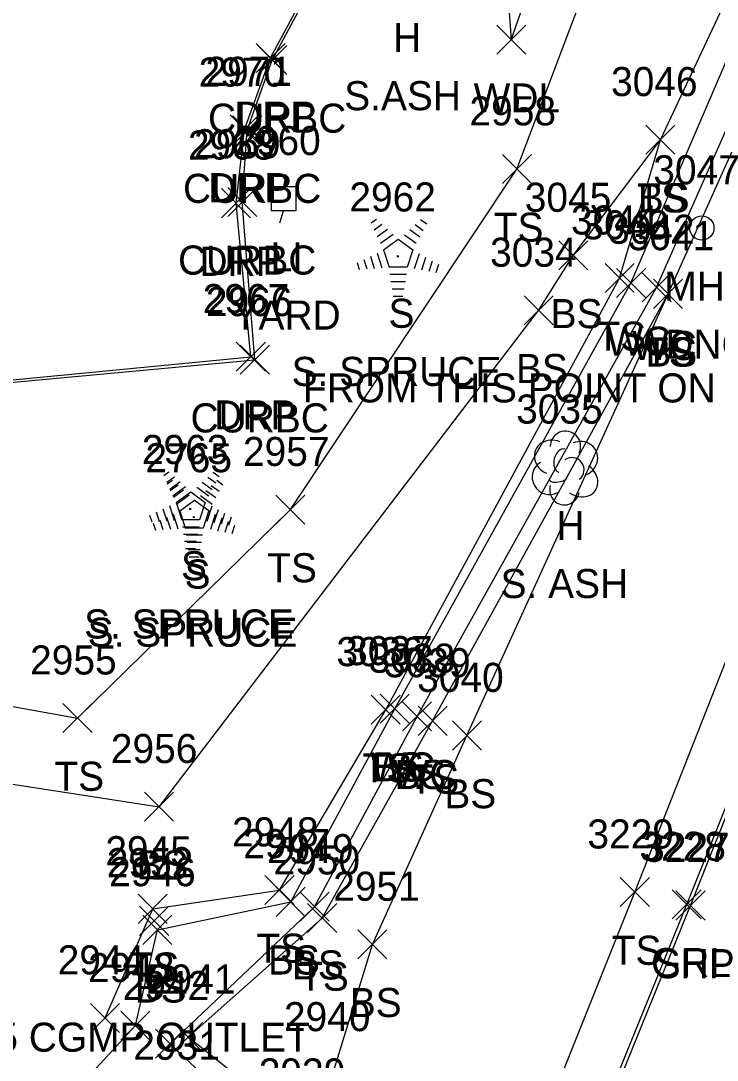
# Model space of a CAD drawing. Extents: x 1623612 to 1625808, y 621345 to 627748.
# Drawn here: x 1624785.9 to 1624833.8, y 626674 to 626745.5 of the extents above; entities that cross this region are included whole.
import ezdxf

# ---------------------------------------------------------------- set-up
doc = ezdxf.new("R2010")
doc.units = 0
for name, color, linetype in [('D_A', 7, 'Continuous'), ('D_C', 7, 'Continuous'), ('D_I', 7, 'Continuous'), ('D_TIC', 7, 'Continuous'), ('L_A', 7, 'Continuous'), ('L_C', 7, 'Continuous'), ('L_I', 7, 'Continuous'), ('L_TIC', 7, 'Continuous'), ('LAWA', 7, 'Continuous'), ('LAWE', 7, 'Continuous'), ('LELB', 7, 'Continuous'), ('LTC', 7, 'Continuous'), ('LTD', 7, 'Continuous'), ('P_A', 7, 'Continuous'), ('P_I', 7, 'Continuous'), ('P_TIC', 7, 'Continuous'), ('PSP', 7, 'Continuous'), ('R_A', 7, 'Continuous'), ('R_I', 7, 'Continuous'), ('R_TIC', 7, 'Continuous'), ('RC', 7, 'Continuous'), ('RDP', 7, 'Continuous'), ('RGR', 7, 'Continuous'), ('U_A', 7, 'Continuous'), ('U_C', 7, 'Continuous'), ('U_I', 7, 'Continuous'), ('ULP', 7, 'Continuous'), ('USMH', 7, 'Continuous')]:
    doc.layers.add(name, color=color, linetype=linetype)

msp = doc.modelspace()

# ---------------------------------------------------------------- linework, layer by layer
at = {"layer": 'D_TIC'}
for points in [[(1624794.045, 626682.576), (1624796.045, 626684.576)], [(1624796.045, 626682.576), (1624794.045, 626684.576)]]:
    msp.add_lwpolyline(points, dxfattribs=at)
at = {"layer": 'L_TIC'}
for points in [[(1624818.593, 626743.177), (1624820.593, 626745.177)], [(1624820.593, 626743.177), (1624818.593, 626745.177)], [(1624828.851, 626736.3), (1624830.851, 626738.3)], [(1624830.851, 626736.3), (1624828.851, 626738.3)], [(1624828.851, 626736.3), (1624830.851, 626738.3)], [(1624830.851, 626736.3), (1624828.851, 626738.3)], [(1624818.983, 626734.285), (1624820.983, 626736.285)], [(1624820.983, 626734.285), (1624818.983, 626736.285)], [(1624822.862, 626728.341), (1624824.862, 626730.341)], [(1624824.862, 626728.341), (1624822.862, 626730.341)], [(1624826.042, 626726.781), (1624828.042, 626728.781)], [(1624828.042, 626726.781), (1624826.042, 626728.781)], [(1624826.827, 626726.445), (1624828.827, 626728.445)], [(1624828.827, 626726.445), (1624826.827, 626728.445)], [(1624828.587, 626726.142), (1624830.587, 626728.142)], [(1624830.587, 626726.142), (1624828.587, 626728.142)], [(1624829.376, 626725.7), (1624831.376, 626727.7)], [(1624831.376, 626725.7), (1624829.376, 626727.7)], [(1624829.376, 626725.7), (1624831.376, 626727.7)], [(1624831.376, 626725.7), (1624829.376, 626727.7)], [(1624820.48, 626724.564), (1624822.48, 626726.564)], [(1624822.48, 626724.564), (1624820.48, 626726.564)], [(1624803.409, 626710.861), (1624805.409, 626712.861)], [(1624805.409, 626710.861), (1624803.409, 626712.861)], [(1624809.966, 626697.092), (1624811.966, 626699.092)], [(1624811.966, 626697.092), (1624809.966, 626699.092)], [(1624810.582, 626697.161), (1624812.582, 626699.161)], [(1624812.582, 626697.161), (1624810.582, 626699.161)], [(1624810.582, 626697.161), (1624812.582, 626699.161)], [(1624812.582, 626697.161), (1624810.582, 626699.161)], [(1624812.124, 626696.64), (1624814.124, 626698.64)], [(1624814.124, 626696.64), (1624812.124, 626698.64)], [(1624812.124, 626696.64), (1624814.124, 626698.64)], [(1624814.124, 626696.64), (1624812.124, 626698.64)], [(1624788.776, 626696.52), (1624790.776, 626698.52)], [(1624790.776, 626696.52), (1624788.776, 626698.52)], [(1624813.192, 626696.331), (1624815.192, 626698.331)], [(1624815.192, 626696.331), (1624813.192, 626698.331)], [(1624815.553, 626695.322), (1624817.553, 626697.322)], [(1624817.553, 626695.322), (1624815.553, 626697.322)], [(1624794.382, 626690.429), (1624796.382, 626692.429)], [(1624796.382, 626690.429), (1624794.382, 626692.429)], [(1624802.66, 626684.697), (1624804.66, 626686.697)], [(1624804.66, 626684.697), (1624802.66, 626686.697)], [(1624827.095, 626684.553), (1624829.095, 626686.553)], [(1624829.095, 626684.553), (1624827.095, 626686.553)], [(1624803.431, 626683.885), (1624805.431, 626685.885)], [(1624805.431, 626683.885), (1624803.431, 626685.885)], [(1624793.948, 626683.4), (1624795.948, 626685.4)], [(1624795.948, 626683.4), (1624793.948, 626685.4)], [(1624805.075, 626683.544), (1624807.075, 626685.544)], [(1624807.075, 626683.544), (1624805.075, 626685.544)], [(1624805.597, 626682.767), (1624807.597, 626684.767)], [(1624807.597, 626682.767), (1624805.597, 626684.767)], [(1624794.267, 626681.956), (1624796.267, 626683.956)], [(1624796.267, 626681.956), (1624794.267, 626683.956)], [(1624809.051, 626680.957), (1624811.051, 626682.957)], [(1624811.051, 626680.957), (1624809.051, 626682.957)], [(1624790.672, 626675.897), (1624792.672, 626677.897)], [(1624792.672, 626675.897), (1624790.672, 626677.897)], [(1624792.759, 626675.368), (1624794.759, 626677.368)], [(1624794.759, 626675.368), (1624792.759, 626677.368)], [(1624796.378, 626674.575), (1624798.378, 626676.575)], [(1624798.378, 626674.575), (1624796.378, 626676.575)], [(1624795.136, 626674.126), (1624797.136, 626676.126)], [(1624797.136, 626674.126), (1624795.136, 626676.126)]]:
    msp.add_lwpolyline(points, dxfattribs=at)
at = {"layer": 'LAWA'}
msp.add_lwpolyline([(1624818.468, 626759.72), (1624819.593, 626744.177), (1624829.084, 626771.257), (1624837.329, 626780.953)], dxfattribs=at)
at = {"layer": 'LAWE'}
for points in [[(1624811.582, 626698.161), (1624827.827, 626727.445), (1624839.883, 626755.559), (1624854.508, 626791.282), (1624865.188, 626822.166), (1624863.603, 626838.682), (1624877.041, 626871.456), (1624883.444, 626899.539), (1624892.235, 626923.619), (1624898.218, 626954.711), (1624904.056, 626977.329), (1624901.716, 626988.499), (1624911.781, 627009.001), (1624921.884, 627031.33), (1624929.456, 627056.067), (1624940.101, 627078.311), (1624950.821, 627105.472), (1624955.574, 627132.709)], [(1624813.124, 626697.64), (1624829.587, 626727.142), (1624841.501, 626754.138), (1624857.448, 626791.686), (1624868.43, 626821.336), (1624865.238, 626838.41), (1624879.116, 626871.558), (1624886.477, 626898.013), (1624896.019, 626922.69), (1624904.588, 626955.371), (1624910.868, 626977.953), (1624905.744, 626987.138), (1624913.873, 627006.887), (1624923.762, 627031.224), (1624932.19, 627054.844), (1624945.442, 627077.292), (1624954.658, 627105.915), (1624958.353, 627132.157)]]:
    msp.add_lwpolyline(points, dxfattribs=at)
at = {"layer": 'LELB'}
for points in [[(1624791.672, 626676.897), (1624794.948, 626684.4), (1624803.66, 626685.697), (1624810.966, 626698.092), (1624827.042, 626727.781), (1624829.851, 626737.3), (1624838.747, 626756.24), (1624853.548, 626791.281), (1624863.637, 626822.185), (1624862.749, 626839.212), (1624876.275, 626871.335), (1624882.133, 626900.384), (1624891.361, 626924.557), (1624896.004, 626955.284), (1624902.388, 626976.957), (1624900.218, 626989.034), (1624911.374, 627010.707), (1624920.895, 627031.294), (1624927.949, 627056.784), (1624938.809, 627078.176), (1624948.809, 627106.637), (1624954.461, 627133.773), (1624968.841, 627171.22)], [(1624797.705, 626668.245), (1624799.803, 626661.876), (1624805.506, 626669.116), (1624797.378, 626675.575), (1624806.597, 626683.767), (1624814.192, 626697.331), (1624830.376, 626726.7), (1624842.305, 626753.265), (1624860.533, 626793.325), (1624869.625, 626820.054), (1624866.475, 626837.777), (1624879.853, 626871.282), (1624887.324, 626897.259), (1624898.322, 626922.367), (1624907.905, 626956.009), (1624912.471, 626978.91), (1624907.55, 626985.86), (1624917.169, 627005.527), (1624931.028, 627029.024), (1624933.074, 627054.91), (1624944.446, 627056.453), (1624952.685, 627071.762), (1624960.506, 627103.985), (1624966.267, 627131.207)], [(1624615.896, 626533.677), (1624628.341, 626517.814), (1624651.68, 626503.494), (1624672.864, 626496.656), (1624697.836, 626496.764), (1624727.511, 626505.635), (1624746.58, 626521.11), (1624758.573, 626532.541), (1624773.283, 626554.446), (1624786.864, 626579.988), (1624794.421, 626601.786), (1624793.575, 626616.571), (1624811.154, 626643.207), (1624828.095, 626685.553), (1624843.974, 626725.86), (1624856.061, 626759.931), (1624861.861, 626782.945), (1624871.064, 626797.226), (1624885.453, 626829.901), (1624902.652, 626871.205)], [(1624772.623, 626700.607), (1624789.776, 626697.52), (1624804.409, 626711.861), (1624819.983, 626735.285), (1624833.651, 626771.445), (1624837.329, 626780.953)], [(1624771.666, 626695.095), (1624795.382, 626691.429), (1624821.48, 626725.564), (1624823.862, 626729.341), (1624829.851, 626737.3)], [(1624767.34, 626599.866), (1624779.798, 626619.553), (1624789.209, 626641.113), (1624799.803, 626661.876), (1624808.372, 626659.473), (1624809.344, 626665.837), (1624807.315, 626672.99), (1624810.051, 626681.957), (1624816.553, 626696.322), (1624830.376, 626726.7)], [(1624756.888, 626622.129), (1624770.552, 626651.212), (1624793.759, 626676.368), (1624795.267, 626682.956), (1624804.431, 626684.885), (1624811.582, 626698.161)], [(1624770.1, 626619.526), (1624781.312, 626647.033), (1624796.306, 626671.021), (1624802.956, 626667.027), (1624803.205, 626668.432), (1624796.136, 626675.126), (1624806.075, 626684.544), (1624813.124, 626697.64)]]:
    msp.add_lwpolyline(points, dxfattribs=at)
at = {"layer": 'LTC'}
for p, q in [((1624809.967, 626731.572), (1624810.321, 626731.829)), ((1624810.176, 626731.106), (1624810.706, 626731.491)), ((1624813.365, 626731.812), (1624813.784, 626731.508)), ((1624810.386, 626730.641), (1624811.09, 626731.152)), ((1624810.596, 626730.175), (1624811.474, 626730.813)), ((1624812.252, 626730.767), (1624813.061, 626730.179)), ((1624812.623, 626731.116), (1624813.302, 626730.622)), ((1624812.994, 626731.464), (1624813.544, 626731.065)), ((1624810.82, 626729.72), (1624811.832, 626730.454)), ((1624811.832, 626730.454), (1624812.829, 626729.729)), ((1624810.366, 626729.501), (1624810.696, 626728.481)), ((1624810.82, 626729.72), (1624811.207, 626728.526)), ((1624812.829, 626729.729), (1624812.438, 626728.526)), ((1624813.266, 626729.459), (1624812.929, 626728.419)), ((1624808.999, 626728.851), (1624809.151, 626728.383)), ((1624809.455, 626729.068), (1624809.666, 626728.416)), ((1624809.91, 626729.284), (1624810.181, 626728.449)), ((1624813.711, 626729.208), (1624813.424, 626728.324)), ((1624814.156, 626728.958), (1624813.919, 626728.229)), ((1624814.6, 626728.708), (1624814.413, 626728.134)), ((1624812.438, 626728.526), (1624811.207, 626728.526)), ((1624812.399, 626728.026), (1624811.255, 626728.026)), ((1624812.316, 626727.526), (1624811.327, 626727.526)), ((1624812.232, 626727.026), (1624811.4, 626727.026)), ((1624812.148, 626726.526), (1624811.473, 626726.526)), ((1624795.699, 626714.203), (1624796.054, 626714.46)), ((1624799.097, 626714.443), (1624799.516, 626714.139)), ((1624795.909, 626713.737), (1624796.438, 626714.122)), ((1624795.947, 626713.636), (1624796.302, 626713.894)), ((1624796.118, 626713.272), (1624796.822, 626713.783)), ((1624798.355, 626713.747), (1624799.034, 626713.253)), ((1624798.726, 626714.095), (1624799.276, 626713.696)), ((1624799.345, 626713.877), (1624799.765, 626713.572)), ((1624796.157, 626713.171), (1624796.686, 626713.555)), ((1624796.328, 626712.806), (1624797.206, 626713.444)), ((1624796.366, 626712.705), (1624797.07, 626713.216)), ((1624796.552, 626712.351), (1624797.564, 626713.085)), ((1624797.564, 626713.085), (1624798.561, 626712.36)), ((1624797.984, 626713.398), (1624798.794, 626712.809)), ((1624798.603, 626713.18), (1624799.283, 626712.686)), ((1624798.974, 626713.529), (1624799.524, 626713.129)), ((1624796.552, 626712.351), (1624796.939, 626711.157)), ((1624796.576, 626712.239), (1624797.454, 626712.877)), ((1624796.8, 626711.784), (1624797.812, 626712.519)), ((1624797.812, 626712.519), (1624798.809, 626711.794)), ((1624798.561, 626712.36), (1624798.17, 626711.157)), ((1624798.232, 626712.832), (1624799.042, 626712.243)), ((1624794.731, 626711.482), (1624794.884, 626711.014)), ((1624795.187, 626711.699), (1624795.399, 626711.047)), ((1624795.642, 626711.915), (1624795.914, 626711.08)), ((1624796.098, 626712.132), (1624796.429, 626711.112)), ((1624796.346, 626711.565), (1624796.677, 626710.546)), ((1624796.8, 626711.784), (1624797.188, 626710.591)), ((1624798.809, 626711.794), (1624798.418, 626710.591)), ((1624798.999, 626712.089), (1624798.661, 626711.05)), ((1624799.247, 626711.523), (1624798.909, 626710.484)), ((1624799.443, 626711.839), (1624799.156, 626710.954)), ((1624799.888, 626711.589), (1624799.651, 626710.859)), ((1624794.98, 626710.916), (1624795.132, 626710.448)), ((1624795.435, 626711.132), (1624795.647, 626710.481)), ((1624795.89, 626711.349), (1624796.162, 626710.514)), ((1624798.17, 626711.157), (1624796.939, 626711.157)), ((1624799.691, 626711.273), (1624799.404, 626710.388)), ((1624800.136, 626711.023), (1624799.899, 626710.293)), ((1624800.332, 626711.339), (1624800.145, 626710.764)), ((1624800.58, 626710.772), (1624800.393, 626710.198)), ((1624798.131, 626710.657), (1624796.987, 626710.657)), ((1624798.048, 626710.157), (1624797.059, 626710.157)), ((1624798.418, 626710.591), (1624797.188, 626710.591)), ((1624798.38, 626710.091), (1624797.235, 626710.091)), ((1624797.964, 626709.657), (1624797.132, 626709.657)), ((1624798.296, 626709.591), (1624797.308, 626709.591)), ((1624797.88, 626709.157), (1624797.205, 626709.157)), ((1624798.212, 626709.091), (1624797.38, 626709.091)), ((1624798.128, 626708.591), (1624797.453, 626708.591))]:
    msp.add_line(p, q, dxfattribs=at)
at = {"layer": 'LTD'}
msp.add_line((1624823.273, 626714.775), (1624823.273, 626714.775), dxfattribs=at)
msp.add_line((1624823.273, 626714.775), (1624823.273, 626714.775), dxfattribs=at)
msp.add_arc((1624823.32, 626716.209), 1.047, 335.52715, 180.95627, dxfattribs=at)
for centre, major_axis, ratio, start_param, end_param in [((1624822.481, 626715.442), (1.21, -0.512), 0.895232, 1.570796, 4.712389), ((1624824.314, 626715.359), (-1.141, -0.483), 0.949671, 1.570796, 4.712389), ((1624823.064, 626715.233), (-0.208, -0.792), 0.645439, 3.141593, 6.283185), ((1624822.19, 626714.067), (0.584, -1.042), 0.959034, 3.141593, 6.283185), ((1624823.773, 626714.609), (-0.5, 0.667), 0.989748, 3.141593, 6.283185), ((1624824.273, 626713.942), (-1.09, 0.792), 0.841452, 1.570796, 4.712389), ((1624822.815, 626714.025), (-0.625, -0.083), 0.423636, 0, 3.141593), ((1624823.273, 626713.275), (0.265, 1.061), 0.942809, 1.570796, 4.712389)]:
    msp.add_ellipse(centre, major_axis=major_axis, ratio=ratio, start_param=start_param, end_param=end_param, dxfattribs=at)
at = {"layer": 'P_TIC'}
for points in [[(1624830.921, 626683.631), (1624832.921, 626685.631)], [(1624832.921, 626683.631), (1624830.921, 626685.631)]]:
    msp.add_lwpolyline(points, dxfattribs=at)
at = {"layer": 'PSP'}
msp.add_lwpolyline([(1624672.807, 626495.101), (1624698.383, 626495.378), (1624728.623, 626503.816), (1624748.691, 626517), (1624761.941, 626529.218), (1624776.737, 626553.451), (1624787.697, 626579.037), (1624801.888, 626613.103), (1624814.469, 626641.623), (1624831.921, 626684.631), (1624847.725, 626724.263), (1624860.959, 626758.735), (1624875.228, 626795.53), (1624888.443, 626828.311), (1624904.991, 626870.392)], dxfattribs=at)
at = {"layer": 'R_TIC'}
for points in [[(1624802.051, 626741.925), (1624804.051, 626743.925)], [(1624804.051, 626741.925), (1624802.051, 626743.925)], [(1624802.164, 626741.782), (1624804.164, 626743.782)], [(1624804.164, 626741.782), (1624802.164, 626743.782)], [(1624800.262, 626737.004), (1624802.262, 626739.004)], [(1624802.262, 626737.004), (1624800.262, 626739.004)], [(1624800.446, 626736.953), (1624802.446, 626738.953)], [(1624802.446, 626736.953), (1624800.446, 626738.953)], [(1624799.673, 626731.934), (1624801.673, 626733.934)], [(1624801.673, 626731.934), (1624799.673, 626733.934)], [(1624800.106, 626732.023), (1624802.106, 626734.023)], [(1624802.106, 626732.023), (1624800.106, 626734.023)], [(1624800.689, 626721.372), (1624802.689, 626723.372)], [(1624802.689, 626721.372), (1624800.689, 626723.372)], [(1624800.965, 626721.167), (1624802.965, 626723.167)], [(1624802.965, 626721.167), (1624800.965, 626723.167)], [(1624830.663, 626683.706), (1624832.663, 626685.706)], [(1624832.663, 626683.706), (1624830.663, 626685.706)]]:
    msp.add_lwpolyline(points, dxfattribs=at)
at = {"layer": 'RC'}
msp.add_lwpolyline([(1624765.584, 626718.794), (1624801.965, 626722.167), (1624801.106, 626733.023), (1624801.446, 626737.953), (1624803.164, 626742.782), (1624816.784, 626768.154), (1624821.95, 626777.846), (1624823.154, 626783.112), (1624820.558, 626819.574), (1624817.463, 626862.426), (1624818.61, 626865.444), (1624822.619, 626868.101), (1624817.503, 626921.762)], dxfattribs=at)
at = {"layer": 'RDP'}
msp.add_lwpolyline([(1624765.615, 626718.874), (1624801.689, 626722.372), (1624800.673, 626732.934), (1624801.262, 626738.004), (1624803.051, 626742.925), (1624816.679, 626768.195), (1624821.75, 626777.782), (1624822.866, 626783.149), (1624820.38, 626819.571), (1624817.454, 626862.5), (1624818.434, 626865.627), (1624822.364, 626868.137), (1624817.204, 626921.816)], dxfattribs=at)
at = {"layer": 'RGR'}
msp.add_lwpolyline([(1624802.73, 626615.379), (1624814.268, 626641.881), (1624831.663, 626684.706), (1624847.532, 626724.384), (1624860.082, 626758.988), (1624865.632, 626781.554)], dxfattribs=at)
at = {"layer": 'ULP'}
for p, q in [((1624804.109, 626734.908), (1624803.943, 626734.074)), ((1624803.109, 626732.408), (1624803.109, 626734.074)), ((1624803.109, 626734.074), (1624804.776, 626734.074)), ((1624804.776, 626734.074), (1624804.776, 626732.408)), ((1624803.943, 626733.241), (1624803.943, 626733.241)), ((1624804.776, 626732.408), (1624803.109, 626732.408)), ((1624803.693, 626731.574), (1624803.943, 626732.408))]:
    msp.add_line(p, q, dxfattribs=at)
at = {"layer": 'USMH'}
for p, q in [((1624832.7, 626731.23), (1624832.7, 626731.23)), ((1624833.533, 626731.23), (1624833.533, 626731.23))]:
    msp.add_line(p, q, dxfattribs=at)
msp.add_circle((1624832.7, 626731.23), 0.833, dxfattribs=at)

# ---------------------------------------------------------------- texts
at = {"layer": 'D_A'}
msp.add_text('P', height=2, dxfattribs=at).set_placement((1624794.423, 626678.576))
at = {"layer": 'D_C'}
msp.add_text('15 CGMP OUTLET', height=2, dxfattribs=at).set_placement((1624782.707, 626674.576))
at = {"layer": 'D_I'}
msp.add_text('2952', height=2, dxfattribs=at).set_placement((1624791.786, 626686.576))
at = {"layer": 'L_A'}
for s, p in [('H', (1624811.468, 626743.328)), ('WDL', (1624817.01, 626739.177)), ('TS', (1624828.26, 626732.3)), ('BS', (1624828.292, 626732.3)), ('TS', (1624818.392, 626730.285)), ('S', (1624811.158, 626724.364)), ('BS', (1624822.303, 626724.341)), ('TS', (1624825.451, 626722.781)), ('WC', (1624826.134, 626722.445)), ('WC', (1624827.894, 626722.142)), ('TS', (1624828.786, 626721.7)), ('BS', (1624828.817, 626721.7)), ('BS', (1624819.921, 626720.564)), ('H', (1624822.706, 626709.775)), ('S', (1624796.89, 626706.995)), ('TS', (1624802.818, 626706.861)), ('S', (1624797.138, 626706.428)), ('TS', (1624809.375, 626693.092)), ('WC', (1624809.889, 626693.161)), ('BS', (1624810.023, 626693.161)), ('TS', (1624788.186, 626692.52)), ('WC', (1624811.431, 626692.64)), ('BS', (1624811.565, 626692.64)), ('TS', (1624812.601, 626692.331)), ('BS', (1624814.994, 626691.322)), ('BS', (1624793.823, 626686.429)), ('TS', (1624802.069, 626680.697)), ('TS', (1624826.505, 626680.553)), ('TS', (1624793.358, 626679.4)), ('BS', (1624802.872, 626679.885)), ('BS', (1624804.516, 626679.544)), ('TS', (1624805.007, 626678.767)), ('BS', (1624793.708, 626677.956)), ('BS', (1624808.492, 626676.957))]:
    msp.add_text(s, height=2, dxfattribs=at).set_placement(p)
at = {"layer": 'L_C'}
for s, p in [('S.ASH', (1624808.113, 626739.328)), ('S. SPRUCE', (1624804.496, 626720.364)), ('S. ASH', (1624818.863, 626705.775)), ('S. SPRUCE', (1624790.228, 626702.995)), ('S. SPRUCE', (1624790.476, 626702.428))]:
    msp.add_text(s, height=2, dxfattribs=at).set_placement(p)
at = {"layer": 'L_I'}
for s, p in [('3046', (1624826.457, 626740.3)), ('3046', (1624826.457, 626740.3)), ('2958', (1624816.723, 626738.285)), ('2962', (1624808.465, 626732.364)), ('3045', (1624820.523, 626732.341)), ('3044', (1624823.703, 626730.781)), ('3043', (1624824.488, 626730.445)), ('3042', (1624826.248, 626730.142)), ('3041', (1624827.605, 626729.7)), ('3041', (1624827.605, 626729.7)), ('3034', (1624818.141, 626728.564)), ('3035', (1624819.934, 626717.775)), ('2963', (1624794.197, 626714.995)), ('2765', (1624794.445, 626714.428)), ('2957', (1624801.149, 626714.861)), ('3036', (1624807.572, 626701.092)), ('3037', (1624808.243, 626701.161)), ('3037', (1624808.243, 626701.161)), ('2955', (1624786.517, 626700.52)), ('3038', (1624809.786, 626700.64)), ('3038', (1624809.786, 626700.64)), ('3039', (1624810.845, 626700.331)), ('3040', (1624813.128, 626699.322)), ('2956', (1624792.067, 626694.429)), ('2948', (1624800.4, 626688.697)), ('3229', (1624824.828, 626688.553)), ('2945', (1624791.688, 626687.4)), ('2947', (1624801.171, 626687.885)), ('2949', (1624802.807, 626687.544)), ('2950', (1624803.251, 626686.767)), ('2946', (1624791.952, 626685.956)), ('2951', (1624807.358, 626684.957)), ('2944', (1624788.413, 626679.897)), ('2943', (1624790.499, 626679.368)), ('2942', (1624792.876, 626678.126)), ('2941', (1624794.685, 626678.575)), ('2940', (1624803.968, 626675.99)), ('2931', (1624793.613, 626674.021)), ('2939', (1624802.239, 626672.116))]:
    msp.add_text(s, height=2, dxfattribs=at).set_placement(p)
at = {"layer": 'LTC'}
for p in [(1624811.714, 626729.468), (1624797.446, 626712.099), (1624797.695, 626711.532)]:
    msp.add_text('.', height=1.037, rotation=270, dxfattribs=at).set_placement(p)
at = {"layer": 'P_A'}
msp.add_text('SHP', height=2, dxfattribs=at).set_placement((1624829.456, 626679.631))
at = {"layer": 'P_I'}
msp.add_text('3227', height=2, dxfattribs=at).set_placement((1624828.661, 626687.631))
at = {"layer": 'R_A'}
for s, p in [('CURBC', (1624798.747, 626737.782)), ('DRP', (1624800.539, 626737.925)), ('CURBC', (1624797.029, 626732.953)), ('DRP', (1624798.751, 626733.004)), ('CURBC', (1624796.689, 626728.023)), ('DRP', (1624798.161, 626727.934)), ('DRP', (1624799.177, 626717.372)), ('CURBC', (1624797.548, 626717.167)), ('GRL', (1624829.206, 626679.706))]:
    msp.add_text(s, height=2, dxfattribs=at).set_placement(p)
at = {"layer": 'R_I'}
for s, p in [('2970', (1624798.1, 626740.953)), ('2971', (1624798.57, 626741.004)), ('2968', (1624797.365, 626735.934)), ('2969', (1624797.791, 626736.023)), ('2967', (1624798.382, 626725.372)), ('2966', (1624798.603, 626725.167)), ('3228', (1624828.403, 626687.706))]:
    msp.add_text(s, height=2, dxfattribs=at).set_placement(p)
at = {"layer": 'U_A'}
for s, p in [('LI', (1624803.045, 626728.241)), ('MHS', (1624830.117, 626726.23))]:
    msp.add_text(s, height=2, dxfattribs=at).set_placement(p)
at = {"layer": 'U_C'}
for s, p in [('YARD', (1624800.439, 626724.241)), ('DNC', (1624830.188, 626722.23)), ('FROM THIS POINT ON ALL MH OR IN', (1624805.275, 626719.23))]:
    msp.add_text(s, height=2, dxfattribs=at).set_placement(p)
at = {"layer": 'U_I'}
for s, p in [('2960', (1624800.549, 626736.241)), ('3047', (1624829.361, 626734.23))]:
    msp.add_text(s, height=2, dxfattribs=at).set_placement(p)

doc.saveas('drawing.dxf')
